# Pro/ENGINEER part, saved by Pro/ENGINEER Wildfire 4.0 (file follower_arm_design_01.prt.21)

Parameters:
  METRIC = "NO"

Other parameters: PITCH, DRILL_DIAMETER, THREAD_DIAMETER, THREADS_PER_INCH, THREAD_DEPTH, THREAD_LENGTH, DRILL_POINT_ANGLE, DRILL_DEPTH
